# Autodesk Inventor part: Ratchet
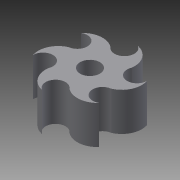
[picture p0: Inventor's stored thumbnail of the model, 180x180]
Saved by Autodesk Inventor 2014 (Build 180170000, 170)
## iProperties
Created: 2013-11
Part Number: Ratchet
Material: Generic
Document SubType Name: Modeling
Designer: 603839
Density: 1 g/cm^3
Appearance: Default
Mass: 4.07709 g
Surface Area: 25.4645 cm^2
Volume: 4.07709 cm^3
Author: 603839
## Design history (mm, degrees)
sketch "Sketch1" dims "d0" = 30.48
  geometry: L1 (0, 15.24)-(13.198, 7.62); L2 (13.198, 7.62)-(13.198, -7.62); L3 (13.198, -7.62)-(0, -15.24); L4 (0, -15.24)-(-13.198, -7.62); L5 (-13.198, -7.62)-(-13.198, 7.62); L6 (-13.198, 7.62)-(0, 15.24); 3 further points
  constraints: 12 end point, 2 coincident, 1 vertical alignment, 15 other
extrude "Extrusion1" new body sketch "Sketch1" distance "d1" = 12.7; taper "d2" = 0 deg
sketch "Sketch2"
  geometry: L1 (-13.198, -7.62)-(0, -15.24) reference; L2 (0, -15.24)-(13.198, -7.62) reference; L3 (13.198, -7.62)-(13.198, 7.62) reference; L4 (13.198, 7.62)-(0, 15.24) reference; L5 (0, 15.24)-(-13.198, 7.62) reference; L6 (-13.198, 7.62)-(-13.198, -7.62) reference; L7 (-13.198, 7.62)-(13.198, -7.62); L8 (13.198, 7.62)-(-13.198, -7.62); L9 (0, -15.24)-(0, 15.24); L10 (0, 15.24)-(0, 11.43); L11 (13.198, 7.62)-(9.899, 5.715); L12 (13.198, -7.62)-(9.899, -5.715); L13 (0, -15.24)-(0, -11.43); L14 (-13.198, -7.62)-(-9.899, -5.715); L15 (-13.198, 7.62)-(-9.899, 5.715); L16 (-13.198, -7.62)-(-9.899, -5.715); C1 r 3.3 at (0, 11.43); C2 r 3.3 at (9.899, 5.715); C3 r 3.3 at (-9.899, 5.715); C4 r 3.3 at (-9.899, -5.715); C5 r 3.3 at (0, -11.43); C6 r 3.3 at (9.899, -5.715); 1 further point
  constraints: 20 end point, 6 centre point, 6 coincident, 6 point on line, 6 tangent, 3 parallel, 1 collinear
  dimensions: "d4" = 3.81 distance of L4.end L10.end; "d5" = 3.81 distance of L3.end L11.end; "d6" = 3.81 distance of L2.end L12.end; "d7" = 3.81 distance of L1.end L13.end; "d8" = 3.81 distance of L5.end L15.end; "d9" = 3.81 distance of L1.start L14.end
extrude "Extrusion2" cut sketch "Sketch2" distance "d10" = 12.7; taper "d11" = 0 deg
sketch "Sketch3"
  geometry: L1 (-13.198, 5.715)-(-13.198, -5.715) reference; L2 (-11.548, -8.573)-(-1.65, -14.287) reference; L3 (1.65, -14.287)-(11.548, -8.572) reference; L4 (13.198, -5.715)-(13.198, 5.715) reference; L5 (11.548, 8.573)-(1.65, 14.288) reference; L6 (-1.65, 14.287)-(-11.548, 8.572) reference; L7 (11.548, -8.572)-(1.65, -14.287); L8 (-1.65, -14.287)-(-11.548, -8.573); L9 (-13.198, -5.715)-(-13.198, 5.715); L10 (-11.548, 8.572)-(-1.65, 14.287); L11 (1.65, 14.288)-(11.548, 8.573); L12 (13.198, 5.715)-(13.198, -5.715); A1 r 3.3 centre (-9.899, 5.715) between (-13.198, 5.715) and (-11.548, 8.572) reference; A2 r 3.3 centre (-9.899, -5.715) between (-11.548, -8.573) and (-13.198, -5.715) reference; A3 r 3.3 centre (0, -11.43) between (1.65, -14.287) and (-1.65, -14.287) reference; A4 r 3.3 centre (9.899, -5.715) between (13.198, -5.715) and (11.548, -8.572) reference; A5 r 3.3 centre (9.899, 5.715) between (11.548, 8.573) and (13.198, 5.715) reference; A6 r 3.3 centre (0, 11.43) between (-1.65, 14.287) and (1.65, 14.288) reference; A7 r 10.846 centre (-6.125, -0.821) between (0, 8.13) and (-11.548, 8.572); A8 r 10.846 centre (-3.773, 4.894) between (7.041, 4.065) and (1.65, 14.288); A9 r 10.846 centre (2.352, 5.715) between (7.041, -4.065) and (13.198, 5.715); A10 r 10.846 centre (6.125, 0.821) between (0, -8.13) and (11.548, -8.572); A11 r 10.846 centre (3.773, -4.894) between (-7.041, -4.065) and (-1.65, -14.287); A12 r 10.846 centre (-2.352, -5.715) between (-7.041, 4.065) and (-13.198, -5.715); A13 r 3.3 centre (-9.899, -5.715) between (-11.548, -8.573) and (-6.864, -7.011); A14 r 3.3 centre (-9.899, 5.715) between (-13.198, 5.715) and (-9.504, 2.439); A15 r 3.3 centre (0, 11.43) between (-1.65, 14.287) and (-2.64, 9.45); A16 r 3.3 centre (9.899, 5.715) between (11.548, 8.573) and (6.864, 7.011); A17 r 3.3 centre (9.899, -5.715) between (13.198, -5.715) and (9.504, -2.439); A18 r 3.3 centre (0, -11.43) between (1.65, -14.287) and (2.64, -9.45); 1 further point
  constraints: 42 point on circle, 18 tangent, 12 centre point, 12 end point, 6 concentric, 2 equal length, 1 point on line
extrude "Extrusion3" cut sketch "Sketch3" distance "d12" = 12.7; taper "d13" = 0 deg
sketch "Sketch4"
  geometry: L1 (-1.65, -14.287)-(0, -15.24) reference; L2 (0, -15.24)-(1.65, -14.287) reference; A1 r 3.3 centre (0, -11.43) between (-1.65, -14.287) and (1.65, -14.287) reference; 1 further point
sketch "Sketch5"
  geometry: L1 (11.548, -8.572)-(13.198, -7.62) reference; L2 (13.198, -7.62)-(13.198, -5.715) reference; A1 r 3.3 centre (9.899, -5.715) between (11.548, -8.572) and (13.198, -5.715) reference; 1 further point
sketch "Sketch6"
  geometry: L1 (13.198, 5.715)-(13.198, 7.62) reference; L2 (13.198, 7.62)-(11.548, 8.573) reference; A1 r 3.3 centre (9.899, 5.715) between (13.198, 5.715) and (11.548, 8.573) reference; 1 further point
sketch "Sketch7"
  geometry: L1 (1.65, 14.288)-(0, 15.24) reference; L2 (0, 15.24)-(-1.65, 14.287) reference; A1 r 3.3 centre (0, 11.43) between (1.65, 14.288) and (-1.65, 14.287) reference; 1 further point
sketch "Sketch8"
  geometry: L1 (-11.548, 8.572)-(-13.198, 7.62) reference; L2 (-13.198, 7.62)-(-13.198, 5.715) reference; A1 r 3.3 centre (-9.899, 5.715) between (-11.548, 8.572) and (-13.198, 5.715) reference; 1 further point
sketch "Sketch9"
  geometry: L1 (-13.198, -5.715)-(-13.198, -7.62) reference; L2 (-13.198, -7.62)-(-11.548, -8.573) reference; A1 r 3.3 centre (-9.899, -5.715) between (-13.198, -5.715) and (-11.548, -8.573) reference; 1 further point
extrude "Extrusion4" cut sketch "Sketch9" distance "d14" = 12.7; taper "d15" = 0 deg
extrude "Extrusion5" cut sketch "Sketch4" distance "d16" = 12.7; taper "d17" = 0 deg
extrude "Extrusion6" cut sketch "Sketch5" distance "d18" = 12.7; taper "d19" = 0 deg
extrude "Extrusion7" cut sketch "Sketch6" distance "d20" = 12.7; taper "d21" = 0 deg
extrude "Extrusion8" cut sketch "Sketch7" distance "d22" = 12.7; taper "d23" = 0 deg
extrude "Extrusion9" cut sketch "Sketch8" distance "d24" = 12.7; taper "d25" = 0 deg
sketch "Sketch10"
  geometry: C1 r 3.175 at (0, 0); 1 further point
  constraints: 1 centre point, 1 coincident
  dimensions: "d26" = 6.35 diameter of C1 (derived)
extrude "Extrusion10" cut sketch "Sketch10" distance "d27" = 12.7; taper "d28" = 0 deg
sketch "Sketch11"
  geometry: A1 r 10.846 centre (2.352, 5.715) between (9.504, -2.439) and (13.198, 5.715) reference; A2 r 10.846 centre (-3.773, 4.894) between (6.864, 7.011) and (1.65, 14.288) reference; A3 r 10.846 centre (-6.125, -0.821) between (-2.64, 9.45) and (-11.548, 8.572) reference; A4 r 10.846 centre (-2.352, -5.715) between (-9.504, 2.439) and (-13.198, -5.715) reference; A5 r 10.846 centre (3.773, -4.894) between (-6.864, -7.011) and (-1.65, -14.287) reference; A6 r 10.846 centre (6.125, 0.821) between (2.64, -9.45) and (11.548, -8.572) reference; A7 r 6.604 centre (-6.928, -3.642) between (-9.504, 2.439) and (-13.198, -5.715); A8 r 6.604 centre (-6.618, 4.179) between (-2.64, 9.45) and (-11.548, 8.572); A9 r 6.604 centre (0.31, 7.821) between (6.864, 7.011) and (1.65, 14.288); A10 r 6.604 centre (6.928, 3.642) between (9.504, -2.439) and (13.198, 5.715); A11 r 6.604 centre (6.618, -4.179) between (2.64, -9.45) and (11.548, -8.572); A12 r 6.604 centre (-0.31, -7.821) between (-6.864, -7.011) and (-1.65, -14.287)
  constraints: 12 point on circle, 6 centre point
  dimensions: "d29" = 6.604 radius of A7 (derived); "d30" = 6.604 radius of A8 (derived); "d31" = 6.604 radius of A9 (derived); "d32" = 6.604 radius of A10 (derived); "d33" = 6.604 radius of A11 (derived); "d34" = 6.604 radius of A12 (derived)
extrude "Extrusion11" join sketch "Sketch11" distance "d35" = 12.7; taper "d36" = 0 deg
hole "Hole1" diameter "d39" = 6.604; stored, may be unused: countersink angle "d43" = 82 deg, drill point angle "d45" = 0 deg; dims "d40" = 19.05, "d41" = 9.525, "d42" = 6.35, "d44" = 25.4, "d46" = 25.4, "d47" = 25.4
body "Solid1"
